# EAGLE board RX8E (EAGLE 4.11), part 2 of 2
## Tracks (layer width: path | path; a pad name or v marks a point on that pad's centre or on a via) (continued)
N$81  (via drill 0.61) (continued)
  Bottom 0.254: v106.05,165.1 98.42,165.1 84.45,151.13 50.8,151.13 44.45,144.78 E39.13 | v115.57,174.63 117.47,176.53 132.08,176.53 133.35,177.8 E24.9 135.89,177.8 137.16,179.07 177.8,179.07 179.07,177.8 E16.9
N$82
  Top 0.254: E24.8 135.25,175.9 141.6,182.25 141.6,189.23 149.86,197.49 177.8,197.49 177.8,190.5 179.71,188.6 E16.13
N$83
  Top 0.254: E15.13 180.97,145.42 182.25,146.69 182.25,173.36 180.97,174.63 E16.8
N$84
  Top 0.254: E19.2 150.5,145.42 153.03,147.96 153.03,177.17 155.57,179.71 155.57,183.52 156.84,184.79 E20.12
N$85  (via drill 0.61)
  Top 0.254: v130.18,142.24 130.18,174.63 127.64,177.17 E24.6
  Bottom 0.254: v130.18,142.24 131.44,140.97 177.8,140.97 179.07,139.7 E15.11
PARITY
  Top 0.254: U$2.AB1 257.18,13.97 253.37,17.78 253.37,183.52 249.56,187.33 E4.15
  Bottom 0.254: 215.9,191.77 161.29,191.77 158.75,189.23 148.59,189.23 147.32,187.96 135.89,187.96 E24.13 | 215.9,191.77 217.17,190.5 E8.1 | 215.9,191.77 243.84,191.77 247.65,187.96 E4.15
PARITY\  (via drill 0.61)
  Top 0.254: v117.47,184.15 117.47,147.96 112.39,142.88 E27.14
  Bottom 0.254: v117.47,184.15 132.08,184.15 133.35,185.42 E24.12
RD  (via drill 0.61)
  Top 0.254: E36.14 67.31,185.42 79.38,185.42 79.38,188.6 80.64,189.87 E32.1 | v159.38,191.77 159.38,182.25 158.12,180.98 E20.10
  Bottom 0.254: v159.38,191.77 158.12,193.04 90.17,193.04 88.9,191.77 83.82,191.77 82.55,190.5 E32.1
RUN  (via drill 0.61)
  Top 0.254: E18.12 156.84,100.97 156.84,99.7 E18.11 158.75,99.06 159.38,99.06 160.66,100.33 160.02,100.97 160.02,128.91 | v161.93,133.35 160.02,131.45 160.02,128.91 | v227.97,107.95 227.97,100.97 226.69,99.7 E6.11 | v165.74,110.49 163.83,112.4 163.83,125.1 160.02,128.91
  Bottom 0.254: v161.93,133.35 177.8,133.35 179.07,134.62 E15.9 | v227.97,107.95 225.43,110.49 v165.74,110.49
RX8_SEL\  (via drill 0.61)
  Top 0.254: v76.2,86.36 76.83,87 76.83,173.36 80.64,177.17 E32.6 | v106.68,83.82 106.68,50.8 104.78,48.9 E25.7
  Bottom 0.254: E1.9 247.65,45.72 245.11,45.72 242.57,48.26 E1.7 240.03,48.26 237.49,45.72 205.74,45.72 204.47,46.99 109.22,46.99 | v76.2,86.36 78.74,83.82 v106.68,83.82 | 109.22,46.99 107.95,48.26 105.41,48.26 E25.7 | 109.22,46.99 110.49,45.72 E25.9
RX_12_BIT\  (via drill 0.61)
  Top 0.254: v147.96,95.25 137.79,105.41 v137.79,154.94 | R7.1 46.35,165.1 47.62,165.1 R16.2
  Bottom 0.254: v147.96,95.25 177.8,95.25 179.07,96.52 E14.10 | v137.79,154.94 126.36,166.37 76.83,166.37 | 76.83,166.37 50.16,166.37 48.9,165.1 R16.2 | 76.83,166.37 71.12,160.66 29.21,160.66 28.57,160.02 DRIVE.FF
RX_DATA  (via drill 0.61)
  Top 0.254: v54.61,58.42 55.24,59.06 55.24,145.42 55.88,146.05 55.88,182.88 57.15,184.15 63.5,184.15 63.5,177.8 65.41,175.9 E36.10
  Bottom 0.254: v54.61,58.42 57.15,55.88 E33.4
RX_DATA\  (via drill 0.61)
  Top 0.254: v169.54,115.57 169.54,102.24 172.09,99.7 E14.4 | v53.34,119.38 46.99,125.73 46.99,149.23 41.91,154.31 41.91,163.2 40.64,164.47 R8.1 41.27,165.1 42.55,165.1 R17.2
  Bottom 0.254: E36.11 64.77,177.8 63.5,176.53 42.55,176.53 37.47,171.45 31.11,171.45 28.57,168.91 27.3,168.91 26.67,168.28 26.67,165.74 27.94,165.74 DRIVE.BB 28.57,165.1 29.84,166.37 38.73,166.37 40.01,165.1 R8.1 | v169.54,115.57 168.28,116.84 55.88,116.84 v53.34,119.38
RX_DONE\
  Top 0.254: R4.1 37.47,165.1 36.2,165.1 R13.2 35.56,165.74 33.66,167.64 33.66,168.91 32.38,170.18 28.57,170.18 DRIVE.X
  Bottom 0.254: E36.5 57.15,180.34 53.98,177.17 41.91,177.17 36.83,172.09 30.48,172.09 28.57,170.18 DRIVE.X
RX_ERROR\
  Top 0.254: R5.1 37.47,190.5 36.2,190.5 R14.2 34.92,190.5 34.92,185.42 28.57,185.42 DRIVE.J
  Bottom 0.254: E36.1 57.15,190.5 55.88,191.77 40.01,191.77 38.73,190.5 R5.1
RX_INIT\
  Top 0.254: 39.37,169.55 39.37,175.9 40.64,177.17 R9.1 | 39.37,169.55 39.37,64.77 42.55,61.6 E37.13 | 39.37,169.55 28.57,180.34 DRIVE.N
RX_OUT\
  Top 0.254: R3.1 73.03,165.1 71.75,165.1 R12.2 71.12,165.74 71.12,184.15 64.77,184.15 64.14,184.79 64.14,186.06 65.41,187.33 E36.15
  Bottom 0.254: DRIVE.RR 27.94,150.5 29.21,151.77 29.21,158.75 27.3,158.75 26.67,159.39 26.67,161.29 66.67,161.29 70.48,165.1 R12.2
RX_RUN\  (via drill 0.61)
  Top 0.254: R6.1 41.27,190.5 42.55,190.5 R15.2 43.18,189.87 49.53,183.52 49.53,128.27 v53.34,124.46 | v154.94,120.65 154.94,106.68 156.84,104.78 E18.13
  Bottom 0.254: v154.94,120.65 151.13,124.46 v53.34,124.46 | DRIVE.D 28.57,190.5 29.84,189.23 38.73,189.23 40.01,190.5 R6.1
RX_SHIFT\
  Top 0.254: R10.2 66.67,165.1 67.94,165.1 R2.1 68.58,165.74 68.58,180.34 66.67,182.25 E36.13
  Bottom 0.254: DRIVE.LL 27.3,154.94 26.04,156.21 24.77,156.21 24.13,156.85 24.13,163.83 64.14,163.83 65.41,165.1 R10.2
RX_TR_REQ\
  Top 0.254: R11.2 36.2,177.8 37.47,177.8 R1.1
  Bottom 0.254: E36.3 57.15,185.42 50.8,179.07 40.01,179.07 38.73,177.8 R1.1 | DRIVE.T 28.57,175.26 31.11,177.8 34.92,177.8 R11.2
SDN_IOT\  (via drill 0.61)
  Top 0.254: v40.64,92.71 41.27,93.35 41.27,97.16 42.55,98.43 E38.11
  Bottom 0.254: v40.64,92.71 15.24,92.71 13.97,93.98 E41.6
SER_IOT\
  Bottom 0.254: E41.5 13.97,96.52 15.24,95.25 40.64,95.25 41.91,93.98 E38.9
SHIFT  (via drill 0.61)
  Top 0.254: v146.69,156.21 146.69,145.42 149.22,142.88 E19.3 | v67.31,169.55 67.94,170.18 67.94,178.44 66.67,179.71 E36.12
  Bottom 0.254: v146.69,156.21 133.35,169.55 v67.31,169.55
SKIP\  (via drill 0.61)
  Top 0.254: v154.94,81.28 154.94,93.98 156.84,95.89 E18.10 | v93.34,78.11 93.34,27.94 84.45,19.05 84.45,13.97 U$2.CS1
  Bottom 0.254: v154.94,81.28 151.76,78.11 v93.34,78.11
STR_IOT\
  Bottom 0.254: E41.4 12.06,99.7 10.79,100.97 10.79,105.41 40.64,105.41 41.91,104.14 E38.13
TP3  (via drill 0.61)
  Top 0.254: v172.72,20.32 199.39,46.99 199.39,67.95 207.65,76.2 207.65,130.18 203.84,133.99 E11.9
  Bottom 0.254: v172.72,20.32 114.94,20.32 108.58,13.97 U$2.CH2
TP3\  (via drill 0.61)
  Top 0.254: E6.5 217.81,97.16 216.53,98.43 216.53,102.24 217.81,103.51 E6.2 217.81,104.78 215.9,106.68 215.9,134.62 203.84,146.69 E11.14 202.56,146.69 200.66,144.78 v200.66,130.18 | E23.8 133.99,132.72 132.72,133.99 132.72,137.8 133.99,139.07 E23.11 133.99,140.34 130.81,143.51 v130.81,191.77
  Bottom 0.254: E23.8 135.89,132.08 137.16,130.81 154.94,130.81 156.21,132.08 E19.8 158.75,132.08 160.66,130.18 v200.66,130.18 | E32.13 90.17,187.96 93.98,191.77 v130.81,191.77 147.32,191.77 148.59,190.5 E20.1
TP4  (via drill 0.61)
  Top 0.254: v188.59,139.7 187.32,138.43 v187.32,41.28
  Bottom 0.254: v188.59,139.7 194.31,139.7 E11.4 | v187.32,41.28 167,20.96 113.67,20.96 106.68,13.97 U$2.CJ2
TR_SKIP\  (via drill 0.61)
  Top 0.254: v58.42,88.9 57.78,88.27 57.78,65.41 55.88,63.5 55.88,13.97 U$2.DB1 | v137.16,91.44 137.16,139.7 135.25,141.61 E23.12 | v197.49,89.54 201.93,93.98 E10.9
  Bottom 0.254: 62.87,89.54 62.23,88.9 v58.42,88.9 | 62.87,89.54 64.77,91.44 E34.8 | 62.87,89.54 135.25,89.54 v137.16,91.44 140.34,88.27 196.22,88.27 v197.49,89.54
VCC  (via drill 0.61)
  Top 0.762: E4.16 248.28,191.14 247.65,191.77 247.65,194.95 C4.1 | E8.14 225.43,191.14 224.79,191.77 224.79,194.95 C8.1 | R5.2 38.73,180.34 40.01,180.34 R6.2 40.64,179.71 42.55,177.8 42.55,170.18 40.64,168.28 R9.2 | E12.14 202.56,191.14 201.93,191.77 201.93,194.95 C12.1 | E16.14 179.71,191.14 179.07,191.77 179.07,194.95 C16.1 | E20.14 156.84,191.14 156.21,191.77 156.21,194.95 C20.1 | E24.14 133.99,191.14 133.35,191.77 133.35,194.95 C24.1 | E28.14 111.12,191.14 110.49,191.77 110.49,194.95 C28.1 | 64.77,192.41 64.77,194.95 C36.1 | 64.77,192.41 64.77,191.77 65.41,191.14 E36.16 | C32.1 87.63,194.95 87.63,191.77 88.27,191.14 E32.14 88.27,189.87 85.09,186.69 85.09,155.58 87.63,153.04 C31.1 | v55.88,190.5 57.78,192.41 64.77,192.41 | E15.14 179.71,147.96 179.07,148.59 179.07,151.77 C15.1 | E7.14 225.43,147.96 224.79,148.59 224.79,151.77 C7.1 | E3.14 248.28,147.96 247.65,148.59 247.65,151.77 C3.1 | E26.14 111.12,107.32 111.12,111.76 C26.1 110.49,112.4 108.58,114.3 108.58,132.72 104.78,136.53 E27.5 | E22.14 133.99,107.32 133.35,107.95 133.35,111.13 C22.1 | E18.14 156.84,107.32 156.21,107.95 156.21,111.13 C18.1 | E2.14 248.28,107.32 247.65,107.95 247.65,111.13 C2.1 | E6.14 225.43,107.32 224.79,107.95 224.79,111.13 C6.1 | C14.1 179.07,111.13 179.07,107.95 179.71,107.32 E14.14 180.97,106.05 183.51,103.51 183.51,73.66 179.07,69.22 C13.1 | E10.14 202.56,107.32 201.93,107.95 201.93,111.13 C10.1 201.93,112.4 201.93,127 | 201.93,127 201.93,130.81 202.56,131.45 E11.8 | 201.93,127 199.39,129.54 199.39,149.23 201.93,151.77 C11.1 | E23.14 133.99,147.96 133.35,148.59 133.35,151.77 C23.1
  Top 0.762: R2.2 67.94,154.94 65.41,152.4 C35.1 64.77,151.77 64.77,148.59 65.41,147.96 E35.14 67.31,147.32 67.31,147.96 73.66,154.31 R3.2 | R8.2 40.64,154.31 41.91,153.04 C39.1 41.91,151.77 45.72,147.96 45.72,134.62 43.81,132.72 E39.8 42.55,131.45 41.91,130.81 41.91,112.4 C38.1 41.91,111.13 41.91,107.95 42.55,107.32 E38.14 | E30.14 88.27,107.32 87.63,107.95 87.63,111.13 C30.1 | C34.1 64.77,111.13 64.77,106.68 E34.14 65.41,106.05 63.5,104.14 63.5,74.93 64.77,73.66 64.77,69.22 C33.1 64.77,67.95 65.41,67.31 65.41,64.14 E33.16 | E41.16 19.68,107.32 19.05,107.95 19.05,111.13 C41.1 | C1.1 247.65,67.95 247.65,64.77 248.28,64.14 E1.16 249.56,62.87 251.46,60.96 251.46,38.74 249.56,36.83 C45.+ | E5.14 225.43,64.14 224.79,64.77 224.79,67.95 C5.1 | C9.1 201.93,67.95 201.93,64.77 202.56,64.14 E9.16 202.56,62.87 200.66,60.96 200.66,38.74 198.75,36.83 C44.+ | E17.14 156.84,64.14 156.21,64.77 156.21,67.95 C17.1 | C42.+ 43.81,36.83 43.81,40.64 48.26,45.09 R20.2 48.26,46.36 45.72,48.9 45.72,60.96 43.81,62.87 E37.14 42.55,64.14 42.55,67.31 41.91,67.95 C37.1 | C40.1 19.05,67.95 19.68,67.31 19.68,64.14 E40.16 | E21.16 133.99,64.14 133.99,68.58 C21.1 | C29.1 87.63,67.95 88.27,67.31 88.27,64.14 E29.14 | C25.1 110.49,67.95 110.49,63.5 E25.16 111.12,62.87 108.58,60.33 108.58,39.37 111.12,36.83 C43.+ 112.39,34.29 112.39,21.59 v114.94,19.05
  Bottom 0.762: C4.1 247.01,195.58 244.47,198.12 236.85,198.12 R19.1 235.59,198.12 233.04,195.58 225.43,195.58 C8.1 224.16,195.58 222.25,197.49 199.39,197.49 | R1.2 38.73,167.64 40.01,167.64 R9.2 | 85.09,197.49 67.31,197.49 65.41,195.58 C36.1 | 85.09,197.49 87,195.58 C32.1 | 107.95,197.49 109.86,195.58 C28.1 | 85.09,197.49 107.95,197.49 | 130.81,197.49 132.72,195.58 C24.1 | 107.95,197.49 130.81,197.49 | 153.67,197.49 155.57,195.58 C20.1 | 130.81,197.49 153.67,197.49 | 176.53,197.49 178.44,195.58 C16.1 | 153.67,197.49 176.53,197.49 | 199.39,197.49 201.29,195.58 C12.1 | 176.53,197.49 199.39,197.49 | v55.88,190.5 51.44,190.5 41.27,180.34 R6.2 | E15.14 181.61,147.32 183.51,149.23 198.12,149.23 201.29,152.4 C11.1 202.56,152.4 205.1,154.94 221.62,154.94 224.16,152.4 C7.1 225.43,152.4 227.33,154.31 245.11,154.31 247.01,152.4 C3.1 | 181.61,113.67 179.71,111.76 C14.1 | 181.61,113.67 199.39,113.67 | 199.39,113.67 201.29,111.76 C10.1 | 199.39,113.67 222.25,113.67 224.16,111.76 C6.1 | C2.1 247.01,111.76 243.84,108.59 230.5,108.59 228.6,106.68 227.33,106.68 E6.14 | 181.61,113.67 173.99,113.67 173.35,113.03 158.12,113.03 156.84,111.76 C18.1 155.57,111.76 153.67,109.86 151.13,109.86 149.86,111.13 134.62,111.13 133.99,111.76 C22.1 132.72,111.76 130.18,111.76 128.27,109.86 113.03,109.86 111.12,111.76 C26.1 | 101.6,151.77 104.14,151.77 105.41,150.5 107.95,150.5 109.86,152.4 C27.1 111.12,152.4 113.03,150.5 130.81,150.5 132.72,152.4 C23.1 133.99,152.4 150.5,152.4 C19.1 151.13,151.77 151.76,151.77 156.21,147.32 E19.14 | 101.6,151.77 88.9,151.77 88.27,152.4 C31.1 | R4.2 38.73,154.94 40.01,154.94 R8.2
  Bottom 0.762: C39.1 42.55,152.4 45.09,154.94 R7.2 46.35,154.94 48.26,156.85 66.04,156.85 67.94,154.94 R2.2 | 39.37,113.67 21.59,113.67 19.68,111.76 C41.1 | 39.37,113.67 41.27,111.76 C38.1 | 39.37,113.67 62.23,113.67 64.14,111.76 C34.1 65.41,111.76 80.01,111.76 81.92,113.67 85.09,113.67 87,111.76 C30.1 | 101.6,151.77 101.6,149.23 69.22,149.23 67.31,147.32 E35.14 | 176.53,70.49 178.44,68.58 C13.1 | 176.53,70.49 158.75,70.49 156.84,68.58 C17.1 155.57,68.58 153.67,70.49 130.81,70.49 | 199.39,70.49 201.29,68.58 C9.1 | 176.53,70.49 199.39,70.49 | 222.25,70.49 224.16,68.58 C5.1 | 199.39,70.49 222.25,70.49 | 222.25,70.49 245.11,70.49 247.01,68.58 C1.1 | U$2.BA2 191.77,13.97 191.77,33.66 195.58,33.66 196.85,34.93 C44.+ | U$2.AA2 260.35,13.97 260.35,34.29 249.56,34.29 C45.+ | E40.16 21.59,63.5 23.5,65.41 40.01,65.41 41.91,63.5 E37.14 | 60.33,69.85 59.69,70.49 44.45,70.49 42.55,68.58 C37.1 | 60.33,69.85 61.59,68.58 64.14,68.58 C33.1 | 107.95,70.49 90.17,70.49 88.27,68.58 C29.1 87,68.58 84.45,71.12 61.59,71.12 60.33,69.85 | 107.95,70.49 109.86,68.58 C25.1 | 130.81,70.49 132.72,68.58 C21.1 | 107.95,70.49 130.81,70.49 | v114.94,19.05 127,19.05 127,13.97 U$2.CA2
WRT  (via drill 0.61)
  Top 0.254: v147.32,97.79 145.41,99.7 145.41,160.66 146.05,161.29 132.72,174.63 132.72,178.44 133.99,179.71 E24.10
  Bottom 0.254: E10.5 194.31,96.52 193.04,96.52 191.77,97.79 175.26,97.79 173.99,96.52 E14.5 171.45,96.52 170.18,97.79 v147.32,97.79 | E32.2 80.64,187.33 79.38,186.06 79.38,181.61 132.08,181.61 133.35,180.34 E24.10
XFER_IOT  (via drill 0.61)
  Top 0.254: v217.17,109.22 216.53,109.86 216.53,137.16 205.74,147.96 205.74,170.82 | 205.74,170.82 205.74,182.88 203.84,184.79 E12.12 | v32.38,168.91 32.38,97.16 34.92,94.62 E38.6 | v105.41,170.82 109.86,175.26 109.86,175.9 111.12,177.17 E28.9 | v198.12,170.82 205.74,170.82
  Bottom 0.254: v217.17,109.22 199.39,109.22 196.85,106.68 E10.1 | v32.38,168.91 34.29,170.82 v105.41,170.82 v198.12,170.82
XFER_IOT\  (via drill 0.61)
  Top 0.254: v170.18,144.15 170.81,144.78 170.81,180.98 172.09,182.25 E16.4 | v60.33,100.33 62.23,102.24 v62.23,128.91
  Bottom 0.254: E41.3 13.97,101.6 15.24,100.33 30.48,100.33 34.29,96.52 E38.5 36.83,96.52 38.1,97.79 54.61,97.79 57.15,100.33 v60.33,100.33 | 160.02,143.51 160.66,144.15 v170.18,144.15 | 160.02,143.51 158.75,142.24 E19.12 | v62.23,128.91 64.14,130.81 90.17,130.81 102.87,143.51 160.02,143.51
XFER_REQ  (via drill 0.61)
  Top 0.254: v79.38,113.03 79.38,103.51 80.64,102.24 E30.3 | v40.64,116.21 40.64,139.7 42.55,141.61 E39.12 | v56.52,143.51 56.52,180.98 57.78,182.25 E36.4
  Bottom 0.254: v79.38,113.03 76.2,116.21 v40.64,116.21 | v56.52,143.51 55.24,142.24 44.45,142.24 E39.12

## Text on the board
Bottom: RX8-E Omnibus Interface M8357 | VRS
tPlace: RX8-E Omnibus Interface M8357 | VRS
